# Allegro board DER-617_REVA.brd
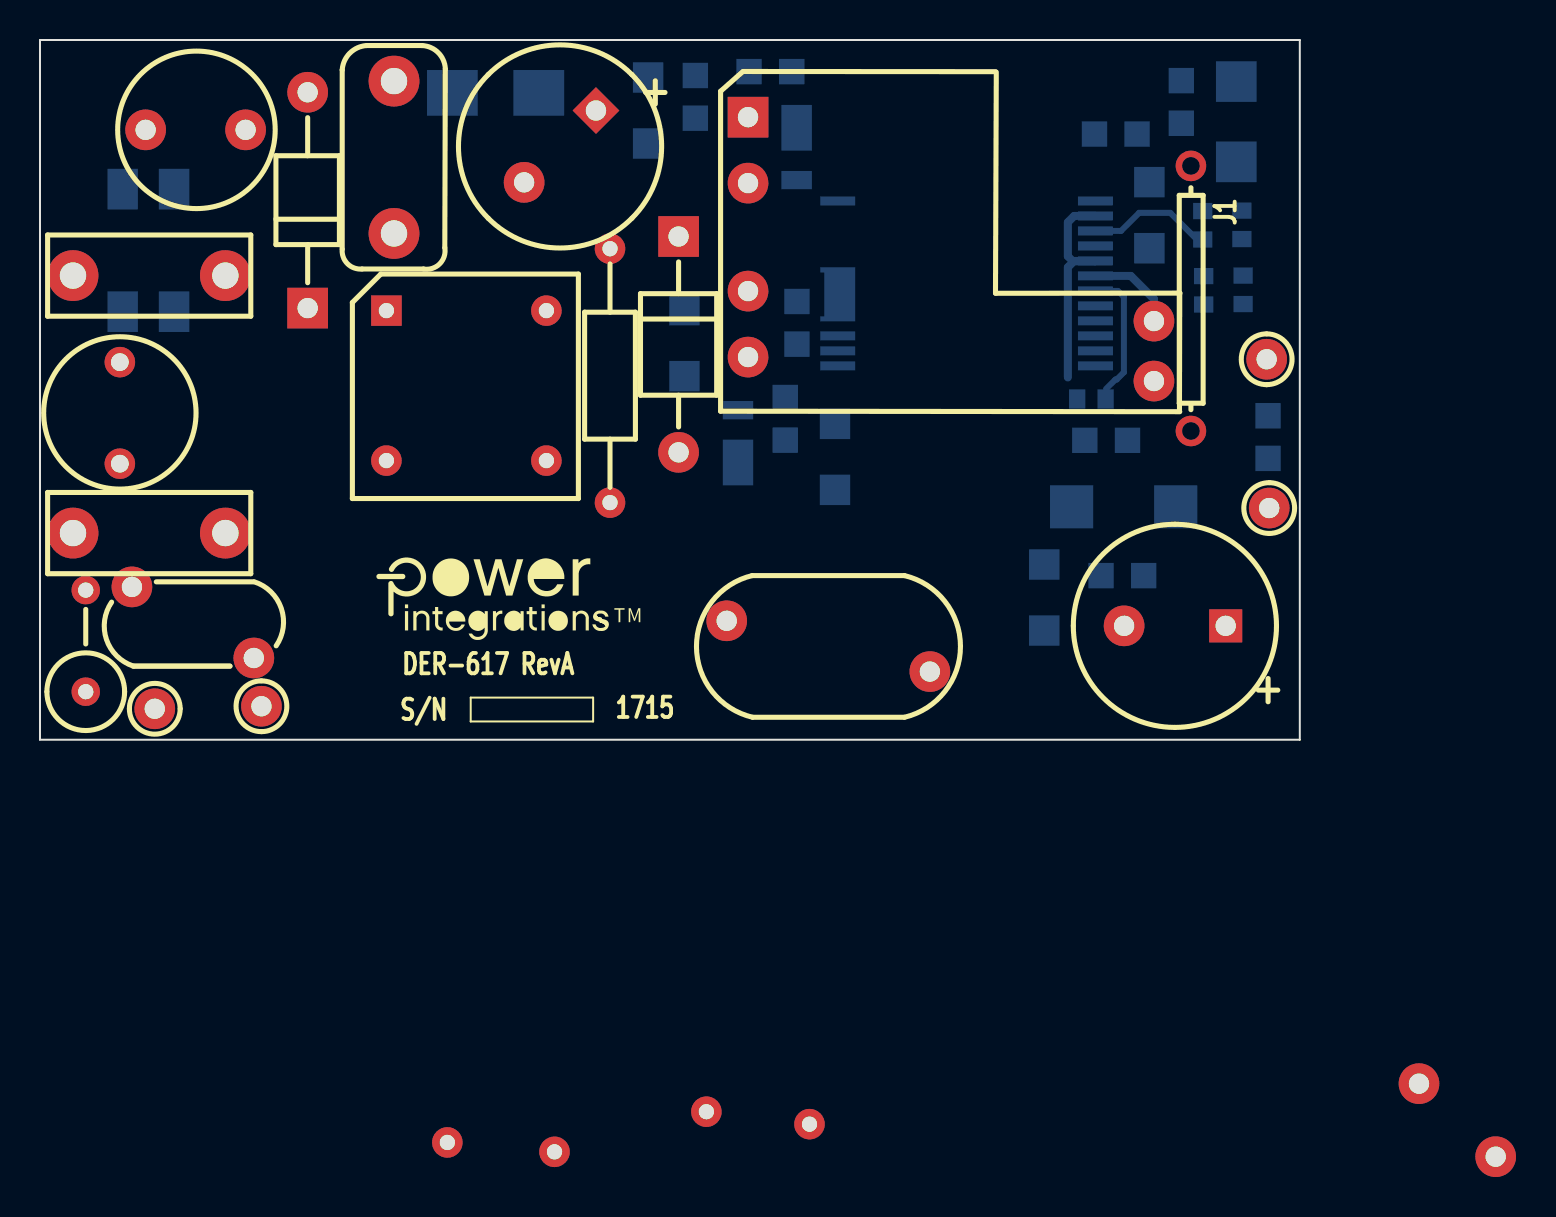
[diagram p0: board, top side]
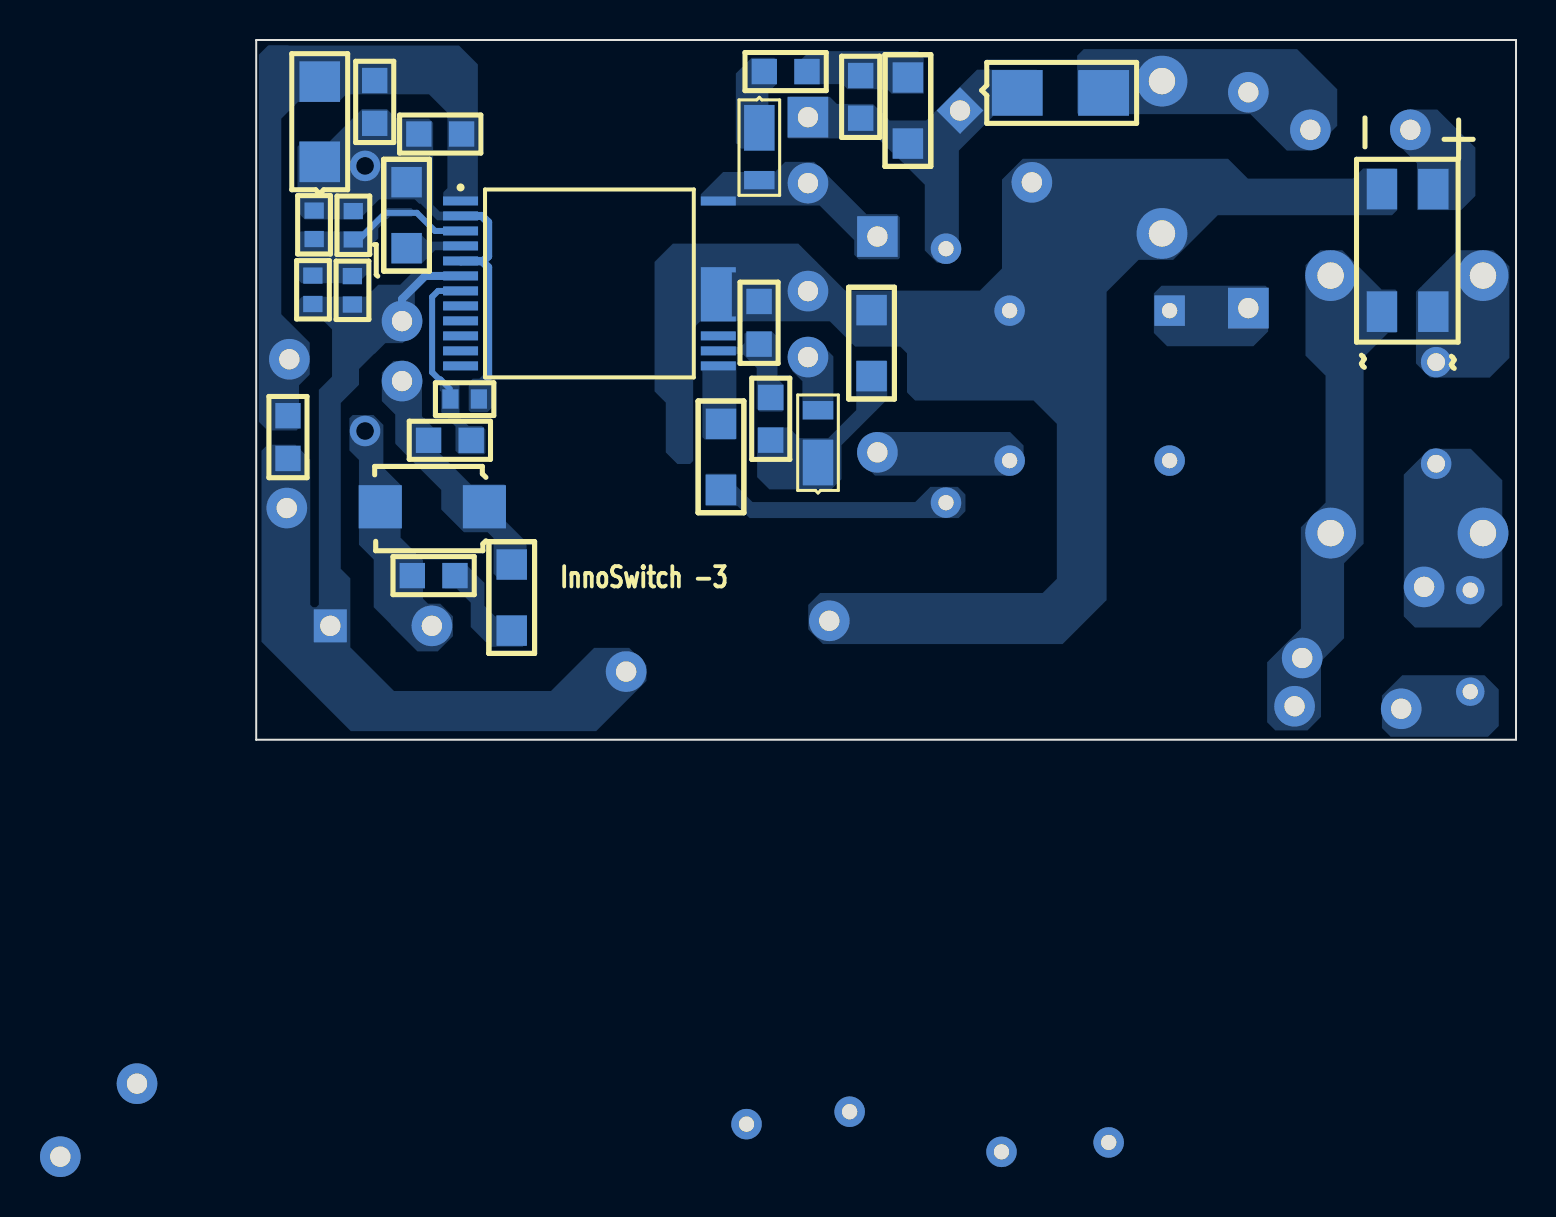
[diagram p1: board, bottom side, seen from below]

Outline 63 x 35 mm; copper layers: TOP, BOTTOM. Coordinates in mm from the lower left corner of the outline.
Outline path: 0,35 0,0 63,0 63,35 0,35

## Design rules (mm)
constraint set DEFAULT: min track width 0.508

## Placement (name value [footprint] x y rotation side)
BR1  B10S-G  [PISMSOIC4]  6.71 21.41 180 bottom
C1  33 nF  [PI_NP_CAP400X160LS300D040]  9.27 10.34 180 top
C2  33 nF  [PI_NP_CAP400X160LS300D040]  9.27 23.22 180 top
C3  100 nF  [PINPCAPRAD440X200300040]  17.7 32.94 270 top
C4  15 uF  [PIPOLCAPCYLD400LS200040]  27.8 31.47 225 top
C5  22 uf  [PISMC1206]  32.23 18.19 90 bottom
C6  470 nF  [PISMC0805]  37.85 19.79 90 bottom
C7  1.5 nF  [PISMC0805]  32.77 33.22 270 bottom
C8  2.2 nF  [PINPYCAPRAD540X290LS400040]  34.34 5.95 0 top
C9  680 pf  [PISMC0805]  53.06 8.21 0 bottom
C10  470 uF  [PIPOLCAPCYLD400LS200040]  59.29 5.7 180 top
C11  330 pF  [PISMC0603]  60.1 26.47 270 bottom
C12  2.2 uF  [PISMC1206]  55.48 27.89 270 bottom
C13  1 uF  [PISMC0805]  61.41 14.07 90 bottom
C14  100 nF  [PISMC0603]  60.17 21.79 90 bottom
C15  68 pF  [PISMC0603]  53.29 17.04 180 bottom
D1  UF4005  [PIDV200X110X040DO41]  13.39 21.59 90 top
D2  ES1J-LTP  [PISMDO214AC12]  24.94 32.35 180 bottom
D3  DFLU1200-7  [PISMDDFLR120012]  34.91 13.84 270 bottom
D4  DFLR1600-7  [PISMDDFLR120012]  37.84 30.63 90 bottom
D5  BYV26C  [PIDV200X150X040SOD57]  31.93 25.17 270 top
D6  SK3200B-LTP  [PISMSMB]  51.59 11.65 0 bottom
D7  US1B  [PISMDSMA]  59.82 28.91 90 bottom
F1  3.15 A  [PI_V_AX_3-6X10_145LS200D030]  2.29 2.4 90 top
L  BLUE  [PITPKEYSTONE100X100]  5.74 1.55 90 top
L1  1 mH  [PICHOKE030DIALS200035]  3.99 13.81 90 top
L2  1.8 mH  [PI_CHOKE_2P_LS200D300]  5.28 30.51 0 top
N  WHT  [PITPKEYSTONE100X100]  11.07 1.68 0 top
NOREF  -  []  -228.6 -144.78 0 top
NOREF#2  -  []  0 0 0 top
NOREF#3  -  []  16.84 9.55 0 top
NOREF#4  -  []  -150.78 54.23 0 top
NOREF#5  -  []  0 0 90 top
R1  10 k  [PISMR0805]  37.27 14.99 90 bottom
R2  0.0  [PISMR0805]  35.46 33.42 0 bottom
R3  1 M  [PISMR1206]  30.41 29.82 90 bottom
R4  2.4 M  [PI14WVRESD100LS100D030]  28.51 24.56 270 top
R5  2.00 M  [PISMR1206]  39.76 12.5 90 bottom
R6  47  [PISMR0805]  52.25 14.98 0 bottom
R7  47  [PISMR1206]  50.22 5.46 90 bottom
R8  102 k  [PISMR0603]  58.19 21.77 90 bottom
R9  5.62 k  [PISMR0603]  58.15 25.02 90 bottom
R10  0.1  [PISMR0805]  52.73 30.3 0 bottom
R11  1.00  [PISMR0805]  57.07 32.97 270 bottom
RTN  BLK  [PITPKEYSTONE100X100]  61.34 19.03 0 top
RV1  275 Vac  [PIDISC350X160LS210X140040]  10.69 4.09 180 top
T1  EE1621  [PI_BOBBIN_EE1621_8P]  35.41 31.14 0 top
T2  EE10  [PI_BOBBIN_EE10_8P]  17.32 21.46 0 top
U1  INN3163C  [PI_IC_INSOP_24D]  52.78 26.95 180 bottom
UNK+V  RED  [PITPKEYSTONE100X100]  61.47 11.59 0 top

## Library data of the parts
BR1 = DIODE BRIDGE_~~+-: alternate symbols: (pi_sm_soic4_slot)
C1 C2 C5-C7 C9 C11-C15 = CAP NP
C3 = CAP NP: alternate symbols: (pinpcaprad440x200300040h)
C4 C10 = CAP POL: alternate symbols: (pipolcapcyld400ls200040800h)
C8 = CAP NP: alternate symbols: (pinpycaprad540x290ls400040h)
D1 = DIODE: alternate symbols: (pidax475x125040do41,pidax390x125040do41)
D2-D4 D7 = DIODE
D5 = DIODE: alternate symbols: (pidax425x150040sod57)
D6 = DIODE SCHOTTKY
F1 = FUSE: alternate symbols: (pi_axial_3_6x10_145ls500d030)
L N RTN UNK+V = TESTPOINT
L1 L2 = INDUCTOR
R1-R3 R5-R11 = R
R4 = R: alternate symbols: (pi14wvresd100ls200d030,pi14wresd100ls400d030,pi14wresd100ls500d030)
RV1 = VARISTOR: alternate symbols: (pi_disc_354x220_ls220x10_040_h)
T1 = BEE16_8P/GENERIC
T2 = BEE10_8P/VERT
U1 = DEV_Inno3CE

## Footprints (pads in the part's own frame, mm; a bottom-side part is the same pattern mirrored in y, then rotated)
PI14WVRESD100LS100D030
  round 1.524 hole 0.762: 1(0,0) 2(12.7,0)
PI_BOBBIN_EE10_8P
  rect 1.524x1.524 hole 0.762: 1(0,0)
  round 1.524 hole 0.762: 2(8.407,-42.073) 3(3.048,-41.603) 4(0,-7.501) 5(8.001,-7.501) 6(21.158,-40.688) 7(16.002,-40.066) 8(8.001,0)
PI_BOBBIN_EE1621_8P
  rect 2.032x2.032 hole 1.016: 1(0,0)
  round 2.032 hole 1.016: 2(0,-3.3) 3(0,-8.7) 4(0,-12) 5(20.3,-13.2) 6(20.3,-10.2) 7(33.554,-48.341) 8(37.389,-51.994)
PI_CHOKE_2P_LS200D300
  round 2.032 hole 1.016: 1(0,0) 2(5,0)
PI_IC_INSOP_24D
  rect 1.75x0.45 smd: 1(0,0) 2(0,-0.75) 3(0,-1.5) 4(0,-2.25) 5(0,-3) 6(0,-3.75) 7(0,-4.5) 8(0,-5.25) 9(0,-6) 10(0,-6.75) 11(0,-7.5) 12(0,-8.25) 13(12.89,-8.25) 14(12.89,-7.5) 15(12.89,-6.75) 24(12.89,0)
  custom 0.438x0.438 smd: 16(12.89,-4.67)
PI_NP_CAP400X160LS300D040
  round 2.54 hole 1.321: 1(0,0) 2(7.62,0)
PI_V_AX_3-6X10_145LS200D030
  round 1.422 hole 0.762: 1(0,0) 2(5.08,0)
PICHOKE030DIALS200035
  round 1.524 hole 0.889: 1(0,0) 2(5.08,0)
PIDISC350X160LS210X140040
  round 2.032 hole 1.016: 1(0,0) 2(6.096,-3.556)
PIDV200X110X040DO41
  rect 2.032x2.032 hole 1.016: 1(0,0)
  round 2.032 hole 1.016: 2(10.795,0)
PIDV200X150X040SOD57
  rect 2.032x2.032 hole 1.016: 1(0,0)
  round 2.032 hole 1.016: 2(10.795,0)
PINPCAPRAD440X200300040
  round 2.54 hole 1.321: 1(0,0) 2(7.62,0)
PINPYCAPRAD540X290LS400040
  round 2.032 hole 1.016: 1(0,0) 2(10.16,-2.54)
PIPOLCAPCYLD400LS200040
  rect 1.651x1.651 hole 1.016: 1(0,0)
  round 2.032 hole 1.016: 2(5.08,0)
PISMC0603
  rect 0.813x0.965 smd: 1(0,0) 2(1.422,0)
PISMC0805
  rect 1.27x1.27 smd: 1(0,0) 2(2.134,0)
PISMC1206
  rect 1.524x1.524 smd: 1(0,0) 2(3.302,0)
PISMDDFLR120012
  rect 2.286x1.524 smd: 1(-0.025,0)
  rect 0.914x1.524 smd: 2(-2.642,0)
PISMDO214AC12
  rect 2.54x2.286 smd: 1(0,0) 2(4.318,0)
PISMDSMA
  rect 2.032x2.032 smd: 1(0,0) 2(4.013,0)
PISMR0603
  rect 0.813x0.965 smd: 1(0,0) 2(1.422,0)
PISMR0805
  rect 1.27x1.27 smd: 1(0,0) 2(2.134,0)
PISMR1206
  rect 1.524x1.524 smd: 1(0,0) 2(3.302,0)
PISMSMB
  rect 2.159x2.159 smd: 1(0,0) 2(5.207,0)
PISMSOIC4
  rect 1.524x2.032 smd: 1(0,0) 2(2.571,0) 3(2.571,6.129) 4(0,6.129)
PITPKEYSTONE100X100
  round 2.032 hole 1.016: 1(0,0)

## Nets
NC8: U1.8
NC9: U1.9
NC10: U1.10
NC11: U1.11
NC12: U1.12
NC15: U1.15
N10967118: C5.1 D3.1 R1.1
N10967192: D4.1 R2.2
N10967272: D4.2 D5.1 T1.2 U1.24
N10967292: C4.1 C7.2 D2.1 R3.1 R4.1 T1.1
N10967352: C6.1 R1.2 U1.14
N10967360: C11.2 C14.2 R8.2 R9.1 U1.3
N10967588: C8.2 C10.1 C13.1 C14.1 R8.1 T1.6 U1.6 UNK+V.1
N10967778: C9.2 C10.2 C11.1 C12.1 C15.2 D6.2 D7.1 R9.2 R10.2 R11.2 U1.2 U1.5
N10967790: C13.2 D7.2 R10.1 R11.1 RTN.1 U1.1
N10968562: BR1.4 C3.2 C4.2 C5.2 C6.2 C8.1 T1.3 T2.8 U1.16
N10970421: F1.1 L.1
N10970473: BR1.1 C1.1 C2.1 N.1 RV1.1
N10970939: C3.1 D1.2 D2.2 L2.2
N10975943: C7.1 R2.1 R3.2
N11207743: C1.2 F1.2 L1.1 RV1.2
N11207906: BR1.3 L2.1
N11317958: R5.2 U1.13(VPIN)
N11319179: C12.2 U1.4
N11357409: D6.1 R6.2 R7.2 T1.5
N11358599: C15.1 R6.1 U1.7
N11365787: R4.2 R5.1
N11380849: D3.2 T1.4
N11384119: BR1.2 C2.2 L1.2
N11395895: D1.1 T2.1
N11395976: D5.2 T2.5
N11401626: C9.1 R7.1

Pads without a net: T1 7 8; T2 2 3 4 6 7

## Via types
v1: diameter 1.524, hole 0.889, TOP to BOTTOM, 2 vias

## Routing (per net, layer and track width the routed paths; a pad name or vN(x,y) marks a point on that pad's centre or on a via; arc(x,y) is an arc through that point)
N10967360: length 6.6
  BOTTOM w0.3: U1.3 54.06,25.45 54.97,26.35 56.53,26.35 57.93,24.95 58.43,24.95
N10967588: length 4.5
  BOTTOM w0.4: T1.6 55.71,22.04 54.55,23.2 U1.6
N10967778: length 11.7
  BOTTOM w0.4: 51.4,18.12 51.4,23.63 51.7,23.93 52.76,23.93 U1.5 51.63,23.95 51.4,24.18 51.4,25.88 51.72,26.2 U1.2
  vias: v1(57.56,28.7) v1(57.56,15.44)
N11358599: length 6.5
  BOTTOM w0.3: U1.7 53.9,22.45 54.2,22.15 54.2,18.38 53.84,18.02 53.78,18.02 53.31,17.55

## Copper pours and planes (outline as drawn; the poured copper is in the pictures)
N10967118 on BOTTOM: 32.99,18.95 32.97,18.97 31.5,18.97 31.45,18.92 31.45,17.02 33.73,14.73 33.73,13.03 34.24,12.52 37.34,12.52 37.95,13.13 37.95,15.6 37.92,15.62 36.37,15.62 35.84,15.09 34.39,15.09 32.99,16.48
N10967192 on BOTTOM: 38.23,34.11 39.01,33.32 39.01,29.84 38.73,29.57 37.54,29.57 37.39,29.72 37.39,32.38 37.01,32.77 37.01,34.04 37.08,34.11
N10967272 on BOTTOM: 40.77,26.72 40.77,27.28 39.65,28.4 37.06,28.4 36.55,28.91 35.1,28.91 32.49,26.29 30.96,26.29 30.81,26.14 30.81,24.1 30.89,24.03 32.87,24.03 33.1,24.26 33.1,24.99 34.82,26.72
N10967292 on BOTTOM: 27.86,29.46 27.86,24.26 28.26,23.86 28.96,23.86 29.57,24.47 29.57,27.76 31.04,29.24 31.06,29.24 31.9,30.07 36.37,30.07 36.42,30.12 36.42,32.08 36.35,32.16 34.32,32.16 33.96,31.8 32.16,31.8 31.33,30.98 29.49,30.98 26.95,33.52 23.96,33.52 23.93,33.48 23.93,31.34 23.95,31.32 26.01,31.32
N10967352 on BOTTOM: 38.58,20.32 38.58,19.84 38.76,19.66 40.72,19.66 40.74,19.63 40.74,19.28 38.66,19.28 37.97,18.59 37.97,16.56 37.82,16.41 36.7,16.41 36.63,16.48 36.63,17.75 36.93,18.06 36.93,20.14 37.21,20.42 38.46,20.42 38.56,20.32
N10967360 on BOTTOM: 60.88,25.35 60.88,22.99 60.73,22.83 57.91,22.83 57.35,23.39 57.35,24.61 56.9,25.07 56.9,25.58 56.31,26.16 55.22,26.16 55.14,26.24 55.14,26.49 55.24,26.59 56.52,26.59 56.95,26.16 56.97,26.16 57.71,25.43 60.81,25.43
N10967588 on BOTTOM: 60.91,21.26 60.64,20.99 59.68,20.99 59.21,20.52 59.21,18.16 59.87,17.5 59.87,6.76 59.99,6.63 60.17,6.63 60.3,6.76 60.3,14.02 61.04,14.76 62.43,14.76 62.74,14.45 62.74,4.9 58.27,0.43 46,0.43 43.48,2.95 43.48,3.73 44.35,4.6 46.1,4.6 48.26,2.44 56.11,2.44 58.29,4.62 58.29,8.08 58.78,8.56 58.78,16.84 57.86,17.75 57.86,18.54 57.1,19.3 57.07,19.3 56.54,19.84 55.68,19.84 55.07,20.45 55.07,22.4 54.51,22.96 54.51,23.19 54.61,23.29 55.27,23.29 55.8,22.76 56.9,22.76 57.49,22.16 60.71,22.16 60.91,21.96
N10967778 on BOTTOM: 52.27,16.38 51.44,16.38 51.08,16.74 51.08,18.14 51.31,18.36 51.54,18.36 51.84,18.06 52.17,18.06 52.37,17.86 52.37,16.48
N10967778 on BOTTOM: 57.14,16.24 56.64,15.75 56.64,13.61 55.78,12.75 55.78,10.11 54.66,8.99 54.66,7.06 54.41,6.81 53.8,6.81 53.16,6.17 53.16,5.18 53.92,4.42 54.94,4.42 56.26,5.74 56.26,5.77 57.12,6.63 57.12,9.02 57.86,9.75 57.86,14 58.34,14.48 58.34,16.08 58.18,16.24
N10967778 on BOTTOM: 54.03,25.98 51.94,25.98 51.94,26.42 53.82,26.42 54.15,26.75 54.15,30.86 54.36,31.06 55.98,31.06 56.46,31.55 57.71,31.55 59.33,29.92 60.68,29.92 60.93,29.67 60.93,26.39 60.57,26.02 57.85,26.02 56.85,27.03 55.07,27.03
N10967790 on BOTTOM: 61.75,21.29 61.75,31.06 60.91,31.9 58.88,31.9 58.5,32.28 54.36,32.28 53.44,31.37 53.44,27.58 53.64,27.38 53.64,26.77 53.62,26.75 51.97,26.75 51.92,26.8 51.92,33.78 52.86,34.72 61.38,34.72 61.37,34.73 62.4,34.73 62.87,34.26 62.87,15.9 62.43,15.47 60.99,15.47 60.86,15.6 60.86,17.73 60.33,18.26 60.33,19.86
N10968562 on BOTTOM: 20.47,6.99 22.67,4.79 34.66,4.79 35.39,5.52 35.39,6.74 34.8,7.34 23.67,7.34 22.96,8.05 22.96,15.8 24.13,16.97 30.05,16.97 30.45,17.37 30.45,19.33 30.78,19.66 33.05,19.66 34.32,20.93 40.79,20.93 41.15,20.57 41.15,13.94 41.3,13.79 41.94,13.79 42.52,14.38 42.52,16.87 43.08,17.42 43.08,23.9 42.16,24.82 35.89,24.82 33.54,22.47 26.81,22.47 25.7,23.57 25.7,28.02 24.66,29.06 14.4,29.06 13.41,28.07 8.15,28.07 7.65,28.57 6.07,28.57 5.94,28.45 5.94,26.49 6.2,26.24 14.91,26.24 17.14,24 18.87,24 20.47,22.4
N10970421 on BOTTOM: 0.86,2.51 1.57,3.23 5.69,3.23 6.71,2.21 6.71,0.58 6.27,0.15 1.4,0.15 0.86,0.69
N10970473 on BOTTOM: 10.76,5.56 12.45,3.87 12.45,0.88 12.04,0.47 10.43,0.47 9.75,1.14 9.75,3.92 8.6,5.08 8.6,8.83 7.62,9.8 7.62,19.13 6.4,20.35 5.99,20.35 5.94,20.4 5.94,22.43 6.03,22.52 6.72,22.52 8.69,24.49 9.78,24.49 10.53,23.74 10.53,19.22 9.53,18.21 9.53,11.86 10.76,10.63
N10970939 on BOTTOM: 10.95,34.54 8.94,32.54 8.94,30.71 10.19,29.46 11.46,29.46 13.28,31.29 21.89,31.29 21.95,31.34 21.95,34.21 21.62,34.54
N10975943 on BOTTOM: 31.45,32.54 33.43,32.54 33.68,32.79 35.71,32.79 35.84,32.92 35.84,33.93 35.33,34.44 29.9,34.44 29.62,34.16 29.62,32.33 29.64,32.31 31.22,32.31
N11207743 on BOTTOM: 4.32,14.55 2.26,14.55 0.69,12.98 0.69,6.73 1.8,5.61 5.05,5.61 5.61,6.17 5.61,13.26
N11207906 on BOTTOM: 4.93,26.49 2.74,26.49 2.03,27.2 2.03,29.62 3.94,31.52 5.44,31.52 6.22,30.73 6.22,30.1 4.95,28.83 4.95,26.52
N11317958 on BOTTOM: 40.69,18.44 40.74,18.49 40.74,18.9 40.72,18.92 39.04,18.92 38.99,18.87 38.99,15.09 39.07,15.01 40.56,15.01 40.69,15.14
N11319179 on BOTTOM: 51.99,24.92 54.41,24.92 54.81,25.32 56.21,25.32 56.24,25.3 56.24,23.95 56.13,23.85 54.69,23.85 54.05,24.49 51.99,24.49
N11357409 on BOTTOM: 50.52,12.7 50.52,10.92 49.48,9.88 49.48,8.2 49.61,8.08 50.9,8.08 51.13,8.31 51.13,10.08 51.43,10.38 52.61,10.38 53.75,11.52 53.75,12.5 55.71,14.47 55.71,14.48 56.05,14.81 56.05,16.27 56.72,16.94 56.72,18.36 56.13,18.95 55.42,18.95 54.71,18.24 54.71,16.18 53.84,15.3 53.84,14.34 52.27,12.78 50.6,12.78
N11358599 on BOTTOM: 51.54,14.35 51.54,15.52 51.71,15.7 52.37,15.7 52.83,16.15 52.83,17.73 53.09,17.98 53.7,17.98 53.82,17.86 53.82,17.48 53.75,17.4 53.75,16.38 53.04,15.67 53.04,14.45 52.86,14.27 51.61,14.27
N11365787 on BOTTOM: 38.99,13.26 39.04,13.31 40.49,13.31 40.54,13.26 40.54,11.73 40.49,11.68 38.93,11.68 38.33,11.09 27.88,11.09 27.53,11.43 27.53,12.27 27.91,12.65 29.29,12.65 30.05,11.89 38.18,11.89 38.99,12.7
N11380849 on BOTTOM: 34.14,16.03 34.16,16 35.66,16 35.69,16.03 35.69,17.93 36.2,18.44 36.2,19.71 35.86,20.04 35,20.04 34.14,19.18
N11384119 on BOTTOM: 5,22.4 5,18.82 4.29,18.11 1.32,18.11 0.33,19.1 0.33,23.67 1.14,24.49 2.92,24.49
N11395895 on BOTTOM: 17.73,22.71 18.11,22.33 18.11,20.35 17.45,19.68 13.13,19.68 12.4,20.42 12.4,22.61 12.42,22.61 12.52,22.71
N11395976 on BOTTOM: 32.05,13.21 25.15,13.21 24.63,13.73 24.63,14.72 25.3,15.39 32.03,15.39 32.69,14.73 32.69,13.84
N11401626 on BOTTOM: 53.59,7.62 53.54,7.57 52.98,7.57 52.27,6.86 52.27,5.64 51.28,4.65 49.68,4.65 49.5,4.83 49.5,6.1 49.58,6.17 51.05,6.17 51.59,6.71 51.59,7.85 52.51,8.78 53.59,8.78

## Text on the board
Ref Des/Silkscreen Bottom: InnoSwitch -3
Ref Des/Silkscreen Top: S/N | DER-617 RevA | 1715 | J1
PAGE_OUTLINE: 14.  FAB HOUSE LOGO,DATE CODE TO BE IN SILK SCREEN ONLY.DO NOT USE COPPER. | 13.  MATERIAL FR4 COPPER 2oz THICKNESS 0.039"
User.5: FIGURE | FINISHED_SIZE | 0.762 | 0.889 | 1.016 | 1.3208 | DRILL CHART: TOP to BOTTOM | ALL UNITS ARE IN MILLIMETERS | PLATED | QTY | 12 | 2 | 26 | 6
